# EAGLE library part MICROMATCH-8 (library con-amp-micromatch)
MicroMaTch 8 7-215464-8 / 0-215464-8 Drawing Number C-215464 DDEController.pdf
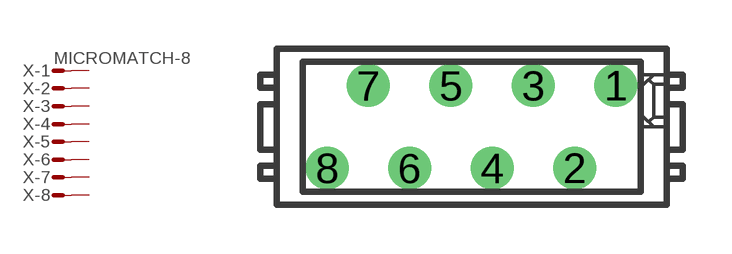
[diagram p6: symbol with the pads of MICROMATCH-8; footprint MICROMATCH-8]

Designator prefix X; gates -1=MV -2=M -3=M -4=M -5=M -6=M -7=M -8=M

## MICROMATCH-8 (MF: FARNELL; MPN: 7-215464-8; OC_FARNELL: 3784642; OC_NEWARK: 26H0301)  [MICROMATCH-8]
1  -1:S  pas
2  -2:S  pas
3  -3:S  pas
4  -4:S  pas
5  -5:S  pas
6  -6:S  pas
7  -7:S  pas
8  -8:S  pas

## Footprint MICROMATCH-8 (pad centres in mm)
MicroMaTch 8 7-215464-8 / 0-215464-8 Drawing Number C-215464 DDEController.pdf
drill 0.813 round: 1 4.445,1.27; 2 3.175,-1.27; 3 1.905,1.27; 4 0.635,-1.27; 5 -0.635,1.27; 6 -1.905,-1.27; 7 -3.175,1.27; 8 -4.445,-1.27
